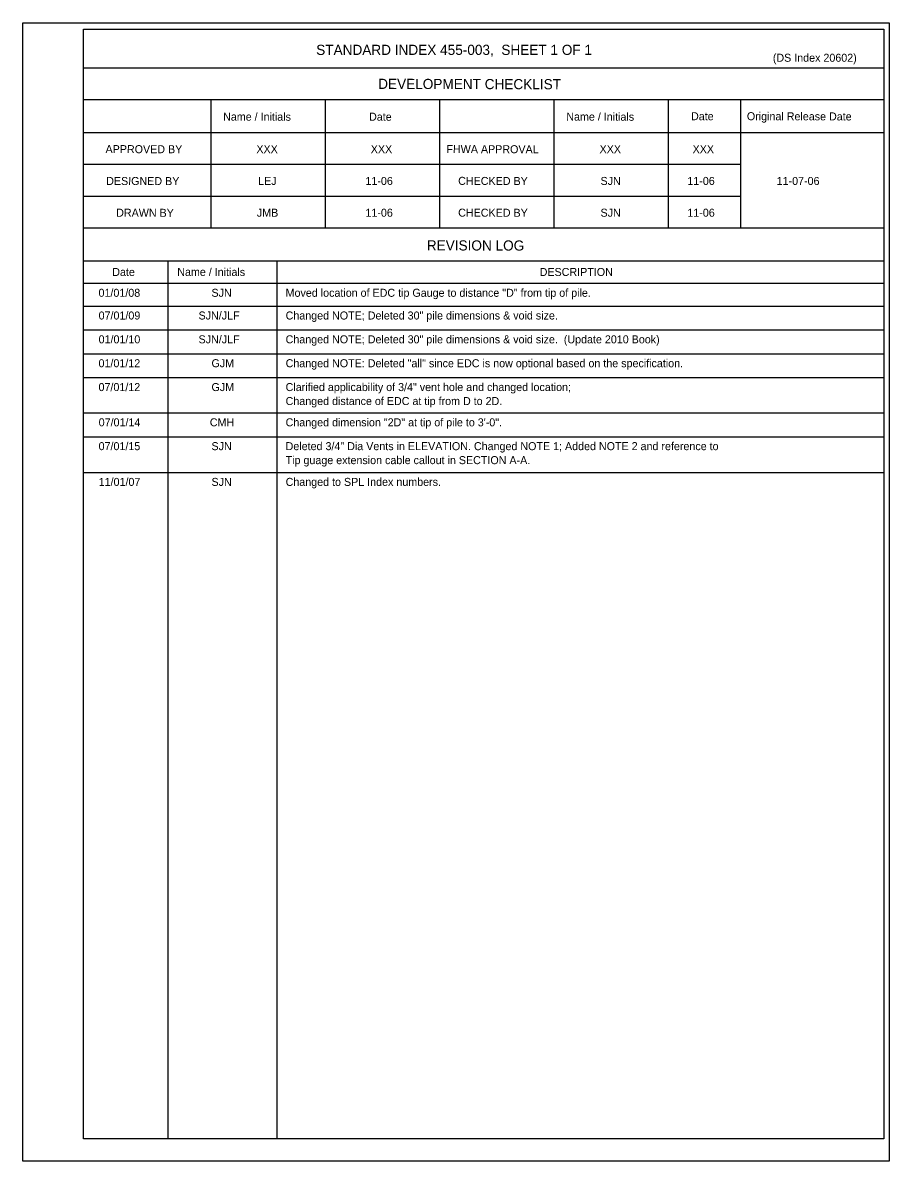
# Model space of a CAD drawing. Extents: x 0 to 36.1, y -3.7 to 15.
# Drawn here: x 25.16 to 36.06, y -0.33 to 14.01 of the extents above; entities that cross this region are included whole.
import ezdxf

# ---------------------------------------------------------------- set-up
doc = ezdxf.new("R2010")
doc.units = 0
for name, color, linetype in [('AdhocPoint_dp', 7, 'Continuous'), ('Patterning', 7, 'Continuous'), ('PlotBorder_dp', 7, 'Continuous'), ('TextMisc', 7, 'Continuous')]:
    doc.layers.add(name, color=color, linetype=linetype)

msp = doc.modelspace()

# ---------------------------------------------------------------- linework, layer by layer
at = {"layer": 'Patterning'}
msp.add_line((25.155, -0.326), (25.155, -0.326), dxfattribs=at)
msp.add_lwpolyline([(25.155, 14.007), (36.062, 14.007), (36.062, -0.326), (25.155, -0.326)], close=True, dxfattribs=at)
at = {"layer": 'PlotBorder_dp'}
for p, q in [((25.921, 10.44), (35.994, 10.44)), ((25.921, 10.14), (35.994, 10.14)), ((25.921, 9.839), (35.994, 9.839)), ((25.921, 9.539), (35.994, 9.539)), ((25.921, 9.095), (35.994, 9.095)), ((25.921, 8.795), (35.994, 8.795)), ((25.921, 8.345), (35.994, 8.345))]:
    msp.add_line(p, q, dxfattribs=at)
at = {"layer": 'TextMisc'}
for p, q in [((35.994, 13.435), (25.921, 13.435)), ((35.994, 13.035), (25.921, 13.035)), ((27.521, 13.035), (27.521, 11.421)), ((28.961, 13.035), (28.961, 11.421)), ((30.401, 13.035), (30.401, 11.421)), ((31.841, 13.035), (31.841, 11.421)), ((33.281, 13.035), (33.281, 11.421)), ((34.188, 13.035), (34.188, 11.421)), ((35.994, 12.621), (25.921, 12.621)), ((34.188, 12.221), (25.921, 12.221)), ((34.188, 11.821), (25.921, 11.821)), ((35.994, 11.421), (25.921, 11.421)), ((35.994, 11.007), (25.921, 11.007)), ((26.981, 11.007), (26.981, -0.046)), ((28.352, 11.007), (28.352, -0.046)), ((35.994, 10.726), (25.921, 10.726))]:
    msp.add_line(p, q, dxfattribs=at)
msp.add_lwpolyline([(25.921, 13.926), (35.994, 13.926), (35.994, -0.046), (25.921, -0.046)], close=True, dxfattribs=at)

# ---------------------------------------------------------------- texts
at = {"layer": 'AdhocPoint_dp'}
for s, height, p in [('STANDARD INDEX 455-003,  SHEET 1 OF 1', 0.128, (28.849, 13.602)), ('(DS Index 20602)', 0.1008, (34.597, 13.516)), ('XXX', 0.1008, (28.096, 12.365)), ('XXX', 0.1008, (29.536, 12.365)), ('XXX', 0.1008, (32.416, 12.365)), ('XXX', 0.1008, (33.587, 12.365)), ('LEJ', 0.1008, (28.118, 11.965)), ('11-06', 0.1008, (29.469, 11.965)), ('SJN', 0.1008, (32.428, 11.965)), ('11-06', 0.1008, (33.521, 11.965)), ('11-07-06', 0.1008, (34.645, 11.965)), ('JMB', 0.1008, (28.102, 11.565)), ('11-06', 0.1008, (29.469, 11.565)), ('SJN', 0.1008, (32.428, 11.565)), ('11-06', 0.1008, (33.521, 11.565)), ('DESCRIPTION', 0.1008, (31.662, 10.819)), ('01/01/08', 0.1008, (26.109, 10.557)), ('SJN', 0.1008, (27.531, 10.557)), ('Moved location of EDC tip Gauge to distance "D" from tip of pile.', 0.1008, (28.464, 10.557)), ('07/01/09', 0.1008, (26.11, 10.271)), ('SJN/JLF', 0.1008, (27.368, 10.271)), ('Changed NOTE; Deleted 30" pile dimensions & void size.', 0.1008, (28.464, 10.271)), ('01/01/10', 0.1008, (26.11, 9.971)), ('SJN/JLF', 0.1008, (27.368, 9.971)), ('Changed NOTE; Deleted 30" pile dimensions & void size.  (Update 2010 Book)', 0.1008, (28.464, 9.971)), ('01/01/12', 0.1008, (26.109, 9.67)), ('GJM', 0.1008, (27.531, 9.67)), ('Changed NOTE: Deleted "all" since EDC is now optional based on the specification.', 0.1008, (28.464, 9.67)), ('07/01/12', 0.1008, (26.109, 9.37)), ('GJM', 0.1008, (27.531, 9.37)), ('Clarified applicability of 3/4" vent hole and changed location;', 0.1008, (28.464, 9.37)), ('Changed distance of EDC at tip from D to 2D.', 0.1008, (28.464, 9.194)), ('07/01/14', 0.1008, (26.111, 8.926)), ('Changed dimension "2D" at tip of pile to 3\'-0".', 0.1008, (28.464, 8.926)), ('CMH', 0.1008, (27.51, 8.926)), ('07/01/15', 0.1008, (26.11, 8.626)), ('SJN', 0.1008, (27.531, 8.626)), ('Deleted 3/4" Dia Vents in ELEVATION. Changed NOTE 1; Added NOTE 2 and reference to', 0.1008, (28.464, 8.626)), ('Tip guage extension cable callout in SECTION A-A.', 0.1008, (28.464, 8.45)), ('11/01/07', 0.1008, (26.111, 8.176)), ('SJN', 0.1008, (27.531, 8.176)), ('Changed to SPL Index numbers.', 0.1008, (28.464, 8.176))]:
    msp.add_text(s, height=height, dxfattribs=at).set_placement(p)
for s, height, p in [('DEVELOPMENT CHECKLIST', 0.128, (29.629, 13.174)), ('Name / Initials', 0.1008, (27.677, 12.775)), ('Date', 0.1008, (29.514, 12.774)), ('Name / Initials', 0.1008, (31.997, 12.775)), ('Date', 0.1008, (33.567, 12.78)), ('Original Release Date', 0.1008, (34.27, 12.78)), ('APPROVED BY', 0.1008, (26.197, 12.366)), ('FHWA APPROVAL', 0.1008, (30.488, 12.366)), ('DESIGNED BY', 0.1008, (26.205, 11.965)), ('CHECKED BY', 0.1008, (30.636, 11.966)), ('DRAWN BY', 0.1008, (26.331, 11.565)), ('CHECKED BY', 0.1008, (30.636, 11.566)), ('REVISION LOG', 0.128, (30.241, 11.141)), ('Date', 0.1008, (26.282, 10.819)), ('Name / Initials', 0.1008, (27.1, 10.82))]:
    msp.add_text(s, height=height, rotation=359.8756, dxfattribs=at).set_placement(p)

doc.saveas('drawing.dxf')
